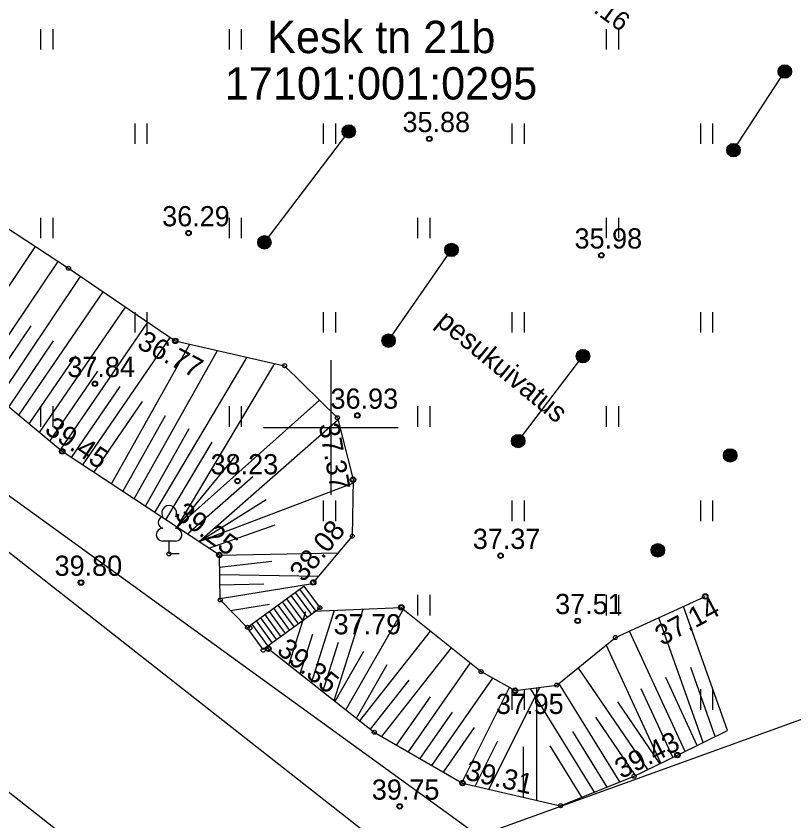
# Model space of a CAD drawing. Extents: x 641898 to 642452, y 6471715 to 6472255.
# Drawn here: x 642038.32 to 642067.2, y 6472085.4 to 6472115.26 of the extents above; entities that cross this region are included whole.
import ezdxf

# ---------------------------------------------------------------- set-up
doc = ezdxf.new("R2010")
doc.units = 0
for name, color, linetype in [('HALJASTUS', 7, 'Continuous'), ('HOONE', 7, 'Continuous'), ('KORGUS-EH2000', 7, 'Continuous'), ('MOOTMPUNKT', 7, 'Continuous'), ('MOOTPIIR', 7, 'Continuous'), ('PIIR', 7, 'Continuous'), ('PUU', 7, 'Continuous'), ('RAJATIS', 7, 'Continuous'), ('RELJEEF', 7, 'Continuous'), ('TEE', 7, 'Continuous'), ('VORK', 7, 'Continuous')]:
    doc.layers.add(name, color=color, linetype=linetype)

msp = doc.modelspace()

# ---------------------------------------------------------------- linework, layer by layer
at = {"layer": 'HALJASTUS'}
for p, q in [((642039.225, 6472114.782), (642039.225, 6472114.021)), ((642039.68, 6472114.782), (642039.68, 6472114.021)), ((642046.225, 6472114.782), (642046.225, 6472114.021)), ((642046.68, 6472114.782), (642046.68, 6472114.021)), ((642060.225, 6472114.782), (642060.225, 6472114.021)), ((642060.68, 6472114.782), (642060.68, 6472114.021)), ((642042.725, 6472111.282), (642042.725, 6472110.521)), ((642043.18, 6472111.282), (642043.18, 6472110.521)), ((642049.725, 6472111.282), (642049.725, 6472110.521)), ((642050.18, 6472111.282), (642050.18, 6472110.521)), ((642056.725, 6472111.282), (642056.725, 6472110.521)), ((642057.18, 6472111.282), (642057.18, 6472110.521)), ((642063.725, 6472111.282), (642063.725, 6472110.521)), ((642064.18, 6472111.282), (642064.18, 6472110.521)), ((642039.225, 6472107.782), (642039.225, 6472107.021)), ((642039.68, 6472107.782), (642039.68, 6472107.021)), ((642046.225, 6472107.782), (642046.225, 6472107.021)), ((642046.68, 6472107.782), (642046.68, 6472107.021)), ((642053.225, 6472107.782), (642053.225, 6472107.021)), ((642053.68, 6472107.782), (642053.68, 6472107.021)), ((642060.225, 6472107.782), (642060.225, 6472107.021)), ((642060.68, 6472107.782), (642060.68, 6472107.021)), ((642042.725, 6472104.282), (642042.725, 6472103.521)), ((642043.18, 6472104.282), (642043.18, 6472103.521)), ((642049.725, 6472104.282), (642049.725, 6472103.521)), ((642050.18, 6472104.282), (642050.18, 6472103.521)), ((642056.725, 6472104.282), (642056.725, 6472103.521)), ((642057.18, 6472104.282), (642057.18, 6472103.521)), ((642063.725, 6472104.282), (642063.725, 6472103.521)), ((642064.18, 6472104.282), (642064.18, 6472103.521)), ((642039.225, 6472100.782), (642039.225, 6472100.021)), ((642039.68, 6472100.782), (642039.68, 6472100.021)), ((642046.225, 6472100.782), (642046.225, 6472100.021)), ((642046.68, 6472100.782), (642046.68, 6472100.021)), ((642053.225, 6472100.782), (642053.225, 6472100.021)), ((642053.68, 6472100.782), (642053.68, 6472100.021)), ((642060.225, 6472100.782), (642060.225, 6472100.021)), ((642060.68, 6472100.782), (642060.68, 6472100.021)), ((642049.725, 6472097.282), (642049.725, 6472096.521)), ((642050.18, 6472097.282), (642050.18, 6472096.521)), ((642056.725, 6472097.282), (642056.725, 6472096.521)), ((642057.18, 6472097.282), (642057.18, 6472096.521)), ((642063.725, 6472097.282), (642063.725, 6472096.521)), ((642064.18, 6472097.282), (642064.18, 6472096.521)), ((642053.225, 6472093.782), (642053.225, 6472093.021)), ((642053.68, 6472093.782), (642053.68, 6472093.021)), ((642060.225, 6472093.782), (642060.225, 6472093.021)), ((642060.68, 6472093.782), (642060.68, 6472093.021)), ((642056.725, 6472090.282), (642056.725, 6472089.521)), ((642057.18, 6472090.282), (642057.18, 6472089.521)), ((642063.725, 6472090.282), (642063.725, 6472089.521)), ((642064.18, 6472090.282), (642064.18, 6472089.521))]:
    msp.add_line(p, q, dxfattribs=at)
at = {"layer": 'HOONE'}
msp.add_lwpolyline([(642065.653, 6472064.719), (642027.624, 6472094.67), (642021.622, 6472087.119), (642059.651, 6472057.168), (642065.653, 6472064.719)], dxfattribs=at)
at = {"layer": 'KORGUS-EH2000'}
for centre in [(642053.663, 6472110.708), (642044.723, 6472107.212), (642060.051, 6472106.387), (642044.229, 6472103.211), (642041.245, 6472101.619), (642050.992, 6472100.443), (642040.033, 6472099.108), (642046.54, 6472098.009), (642050.829, 6472098.064), (642045.866, 6472095.265), (642056.308, 6472095.24), (642040.73, 6472094.242), (642049.352, 6472094.247), (642063.908, 6472093.726), (642052.622, 6472093.318), (642059.17, 6472092.822), (642047.685, 6472091.788), (642056.844, 6472090.234), (642062.871, 6472087.84), (642054.894, 6472086.799), (642052.56, 6472085.936)]:
    msp.add_circle(centre, 0.1, dxfattribs=at)
at = {"layer": 'MOOTMPUNKT'}
for centre in [(642053.663, 6472110.708), (642044.723, 6472107.212), (642060.051, 6472106.387), (642040.265, 6472105.906), (642044.229, 6472103.211), (642048.288, 6472102.29), (642041.245, 6472101.619), (642050.25, 6472100.358), (642050.992, 6472100.443), (642040.033, 6472099.108), (642046.54, 6472098.009), (642050.829, 6472098.064), (642050.8, 6472095.965), (642044, 6472095.306), (642045.866, 6472095.265), (642056.308, 6472095.24), (642040.73, 6472094.242), (642049.352, 6472094.247), (642063.908, 6472093.726), (642045.899, 6472093.597), (642049.598, 6472093.306), (642052.622, 6472093.318), (642059.17, 6472092.822), (642046.91, 6472092.582), (642046.999, 6472092.554), (642060.571, 6472092.204), (642047.494, 6472091.733), (642047.685, 6472091.788), (642055.585, 6472090.939), (642058.392, 6472090.436), (642056.844, 6472090.234), (642051.619, 6472088.689), (642062.871, 6472087.84), (642054.894, 6472086.799), (642061.262, 6472087.055), (642052.56, 6472085.936), (642058.538, 6472085.962)]:
    msp.add_circle(centre, 0.075, dxfattribs=at)
at = {"layer": 'MOOTPIIR'}
msp.add_lwpolyline([(642014.306, 6472085.384), (642027.67, 6472104.979), (642055.501, 6472084.843), (642081.563, 6472094.262), (642123.938, 6472142.273), (642065.721, 6472244.475), (642008.922, 6472196.948), (642003.347, 6472200.453), (641979.65, 6472162.756), (641979.65, 6472162.756), (641986.045, 6472158.736), (642004.269, 6472142.365), (641987.048, 6472123.488), (641970.482, 6472097.889), (641986.758, 6472084.396)], close=True, dxfattribs=at)
at = {"layer": 'PIIR'}
msp.add_line((642016.19, 6472112.51), (642089.96, 6472054.66), dxfattribs=at)
at = {"layer": 'PUU'}
for p, q in [((642044.24, 6472095.781), (642043.76, 6472095.781)), ((642044, 6472095.306), (642044, 6472095.781)), ((642044.38, 6472095.306), (642044, 6472095.306))]:
    msp.add_line(p, q, dxfattribs=at)
for centre, radius, start, end in [((642044, 6472096.826), 0.277, 332.5799, 207.4201), ((642043.83, 6472096.479), 0.233, 109.0217, 253.1415), ((642044.17, 6472096.479), 0.233, 286.8508, 70.9859), ((642043.763, 6472096.018), 0.238, 90.0016, 269.3953), ((642044.237, 6472096.018), 0.238, 270.6047, 89.9984)]:
    msp.add_arc(centre, radius, start, end, dxfattribs=at)
at = {"layer": 'RAJATIS'}
for points in [[(642064.954, 6472110.286), (642066.862, 6472113.206)], [(642047.54, 6472106.867), (642050.672, 6472110.982)], [(642052.148, 6472103.221), (642054.486, 6472106.587)], [(642056.961, 6472099.492), (642059.366, 6472102.644)]]:
    msp.add_lwpolyline(points, dxfattribs=at)
for centre, radius in [((642066.862, 6472113.206), 0.25), ((642066.862, 6472113.206), 0.225), ((642066.862, 6472113.206), 0.2), ((642066.862, 6472113.206), 0.175), ((642066.862, 6472113.206), 0.15), ((642066.862, 6472113.206), 0.125), ((642066.862, 6472113.206), 0.1), ((642066.862, 6472113.206), 0.075), ((642066.862, 6472113.206), 0.05), ((642066.862, 6472113.206), 0.025), ((642050.672, 6472110.982), 0.25), ((642050.672, 6472110.982), 0.225), ((642050.672, 6472110.982), 0.2), ((642050.672, 6472110.982), 0.175), ((642050.672, 6472110.982), 0.15), ((642050.672, 6472110.982), 0.125), ((642050.672, 6472110.982), 0.1), ((642050.672, 6472110.982), 0.075), ((642050.672, 6472110.982), 0.05), ((642050.672, 6472110.982), 0.025), ((642064.954, 6472110.286), 0.25), ((642064.954, 6472110.286), 0.225), ((642064.954, 6472110.286), 0.2), ((642064.954, 6472110.286), 0.175), ((642064.954, 6472110.286), 0.15), ((642064.954, 6472110.286), 0.125), ((642064.954, 6472110.286), 0.1), ((642064.954, 6472110.286), 0.075), ((642064.954, 6472110.286), 0.05), ((642064.954, 6472110.286), 0.025), ((642047.54, 6472106.867), 0.25), ((642047.54, 6472106.867), 0.225), ((642047.54, 6472106.867), 0.2), ((642047.54, 6472106.867), 0.175), ((642047.54, 6472106.867), 0.15), ((642047.54, 6472106.867), 0.125), ((642047.54, 6472106.867), 0.1), ((642047.54, 6472106.867), 0.075), ((642047.54, 6472106.867), 0.05), ((642047.54, 6472106.867), 0.025), ((642054.486, 6472106.587), 0.25), ((642054.486, 6472106.587), 0.225), ((642054.486, 6472106.587), 0.2), ((642054.486, 6472106.587), 0.175), ((642054.486, 6472106.587), 0.15), ((642054.486, 6472106.587), 0.125), ((642054.486, 6472106.587), 0.1), ((642054.486, 6472106.587), 0.075), ((642054.486, 6472106.587), 0.05), ((642054.486, 6472106.587), 0.025), ((642052.148, 6472103.221), 0.25), ((642052.148, 6472103.221), 0.225), ((642052.148, 6472103.221), 0.2), ((642052.148, 6472103.221), 0.175), ((642052.148, 6472103.221), 0.15), ((642052.148, 6472103.221), 0.125), ((642052.148, 6472103.221), 0.1), ((642052.148, 6472103.221), 0.075), ((642052.148, 6472103.221), 0.05), ((642052.148, 6472103.221), 0.025), ((642059.366, 6472102.644), 0.25), ((642059.366, 6472102.644), 0.225), ((642059.366, 6472102.644), 0.2), ((642059.366, 6472102.644), 0.175), ((642059.366, 6472102.644), 0.15), ((642059.366, 6472102.644), 0.125), ((642059.366, 6472102.644), 0.1), ((642059.366, 6472102.644), 0.075), ((642059.366, 6472102.644), 0.05), ((642059.366, 6472102.644), 0.025), ((642056.961, 6472099.492), 0.25), ((642056.961, 6472099.492), 0.225), ((642056.961, 6472099.492), 0.2), ((642056.961, 6472099.492), 0.175), ((642056.961, 6472099.492), 0.15), ((642056.961, 6472099.492), 0.125), ((642056.961, 6472099.492), 0.1), ((642056.961, 6472099.492), 0.075), ((642056.961, 6472099.492), 0.05), ((642056.961, 6472099.492), 0.025), ((642064.83, 6472098.96), 0.25), ((642064.83, 6472098.96), 0.225), ((642064.83, 6472098.96), 0.2), ((642064.83, 6472098.96), 0.175), ((642064.83, 6472098.96), 0.15), ((642064.83, 6472098.96), 0.125), ((642064.83, 6472098.96), 0.1), ((642064.83, 6472098.96), 0.075), ((642064.83, 6472098.96), 0.05), ((642064.83, 6472098.96), 0.025), ((642062.145, 6472095.439), 0.25), ((642062.145, 6472095.439), 0.225), ((642062.145, 6472095.439), 0.2), ((642062.145, 6472095.439), 0.175), ((642062.145, 6472095.439), 0.15), ((642062.145, 6472095.439), 0.125), ((642062.145, 6472095.439), 0.1), ((642062.145, 6472095.439), 0.075), ((642062.145, 6472095.439), 0.05), ((642062.145, 6472095.439), 0.025)]:
    msp.add_circle(centre, radius, dxfattribs=at)
at = {"layer": 'RELJEEF'}
for p, q in [((642036.119, 6472102.358), (642039.042, 6472106.707)), ((642036.893, 6472101.716), (642039.879, 6472106.159)), ((642037.666, 6472101.073), (642040.71, 6472105.603)), ((642038.418, 6472100.449), (642041.556, 6472105.028)), ((642039.191, 6472099.808), (642042.383, 6472104.466)), ((642039.963, 6472099.166), (642043.21, 6472103.904)), ((642037.279, 6472101.395), (642038.878, 6472103.773)), ((642040.793, 6472098.607), (642044.037, 6472103.341)), ((642038.053, 6472100.752), (642039.708, 6472103.216)), ((642041.866, 6472097.9), (642044.776, 6472103.087)), ((642042.703, 6472097.349), (642045.793, 6472102.856)), ((642038.804, 6472100.128), (642040.535, 6472102.653)), ((642043.465, 6472096.847), (642046.904, 6472102.604)), ((642039.577, 6472099.487), (642041.36, 6472102.088)), ((642044.301, 6472096.296), (642047.929, 6472102.371)), ((642040.375, 6472098.883), (642042.184, 6472101.523)), ((642041.21, 6472098.332), (642043.009, 6472100.957)), ((642044.301, 6472096.296), (642049.59, 6472101.008)), ((642042.285, 6472097.625), (642043.868, 6472100.446)), ((642045.113, 6472095.761), (642050.271, 6472100.275)), ((642043.122, 6472097.073), (642044.74, 6472099.957)), ((642043.883, 6472096.572), (642045.6, 6472099.447)), ((642044.301, 6472096.296), (642046.452, 6472098.926)), ((642044.68, 6472096.046), (642047.111, 6472098.174)), ((642045.113, 6472095.761), (642050.827, 6472097.926)), ((642045.113, 6472095.761), (642047.608, 6472097.327)), ((642045.478, 6472095.521), (642047.939, 6472096.384)), ((642045.866, 6472095.265), (642050.278, 6472095.346)), ((642045.875, 6472094.817), (642047.816, 6472095.037)), ((642045.88, 6472094.545), (642049.552, 6472094.484)), ((642045.888, 6472094.156), (642047.513, 6472094.191)), ((642045.898, 6472093.651), (642049.323, 6472094.213)), ((642046.28, 6472093.207), (642047.726, 6472093.444)), ((642048.449, 6472091.186), (642049.083, 6472093.17)), ((642049.288, 6472090.525), (642050.146, 6472093.215)), ((642050.127, 6472089.864), (642051.21, 6472093.259)), ((642050.562, 6472089.522), (642052.702, 6472093.254)), ((642064.732, 6472088.748), (642063.094, 6472093.355)), ((642063.828, 6472088.307), (642062.18, 6472092.938)), ((642048.869, 6472090.855), (642049.342, 6472092.339)), ((642051.088, 6472089.107), (642053.711, 6472092.444)), ((642063.156, 6472087.979), (642061.094, 6472092.443)), ((642049.708, 6472090.195), (642050.295, 6472092.035)), ((642062.257, 6472087.54), (642060.231, 6472091.928)), ((642050.164, 6472089.835), (642051.232, 6472091.696)), ((642051.903, 6472088.525), (642054.491, 6472091.818)), ((642050.959, 6472089.209), (642052.099, 6472091.198)), ((642052.884, 6472087.959), (642055.186, 6472091.259)), ((642061.769, 6472087.302), (642059.192, 6472091.085)), ((642064.28, 6472088.527), (642063.37, 6472091.085)), ((642051.481, 6472088.798), (642052.909, 6472090.615)), ((642053.754, 6472087.457), (642056.014, 6472090.699)), ((642060.736, 6472086.844), (642058.476, 6472090.504)), ((642063.605, 6472088.198), (642062.439, 6472090.723)), ((642054.872, 6472086.812), (642056.641, 6472090.348)), ((642055.871, 6472086.575), (642057.762, 6472090.354)), ((642059.794, 6472086.466), (642057.421, 6472090.309)), ((642057.656, 6472086.165), (642057.656, 6472090.34)), ((642062.706, 6472087.76), (642061.531, 6472090.303)), ((642052.449, 6472088.21), (642053.702, 6472090.006)), ((642062.223, 6472087.524), (642060.664, 6472089.813)), ((642053.318, 6472087.708), (642054.522, 6472089.434)), ((642061.315, 6472087.081), (642059.838, 6472089.25)), ((642054.188, 6472087.206), (642055.343, 6472088.862)), ((642060.265, 6472086.655), (642058.994, 6472088.712)), ((642055.37, 6472086.69), (642056.21, 6472088.369)), ((642057.156, 6472086.279), (642057.156, 6472088.142)), ((642059.323, 6472086.277), (642058.144, 6472088.187))]:
    msp.add_line(p, q, dxfattribs=at)
for points in [[(642024.308, 6472114.721), (642030.362, 6472113.989), (642036.333, 6472108.482), (642040.265, 6472105.906), (642044.229, 6472103.211), (642048.288, 6472102.29), (642050.25, 6472100.358), (642050.829, 6472098.064), (642050.8, 6472095.965), (642049.352, 6472094.247)], [(642046.898, 6472092.573), (642045.899, 6472093.597), (642045.866, 6472095.265), (642040.033, 6472099.108), (642035.046, 6472103.249), (642029.201, 6472104.902), (642019.993, 6472109.094), (642016.735, 6472110.959)], [(642049.365, 6472093.182), (642052.622, 6472093.318), (642055.585, 6472090.939), (642056.844, 6472090.234), (642058.392, 6472090.436), (642060.571, 6472092.204), (642063.908, 6472093.726)], [(642047.617, 6472091.841), (642051.619, 6472088.689), (642054.894, 6472086.799), (642058.538, 6472085.962), (642061.262, 6472087.055), (642062.871, 6472087.84), (642064.732, 6472088.748)]]:
    msp.add_lwpolyline(points, dxfattribs=at)
at = {"layer": 'TEE'}
for p, q in [((642048.523, 6472093.76), (642049.122, 6472092.94)), ((642048.685, 6472093.878), (642049.284, 6472093.058)), ((642048.846, 6472093.996), (642049.445, 6472093.176)), ((642048.2, 6472093.524), (642048.799, 6472092.704)), ((642048.362, 6472093.642), (642048.961, 6472092.822)), ((642047.716, 6472093.17), (642048.315, 6472092.35)), ((642047.877, 6472093.288), (642048.476, 6472092.468)), ((642048.039, 6472093.406), (642048.638, 6472092.586)), ((642047.393, 6472092.935), (642047.992, 6472092.115)), ((642047.554, 6472093.052), (642048.153, 6472092.232)), ((642047.07, 6472092.699), (642047.669, 6472091.879)), ((642047.231, 6472092.817), (642047.83, 6472091.997))]:
    msp.add_line(p, q, dxfattribs=at)
msp.add_lwpolyline([(642049.607, 6472093.294), (642047.497, 6472091.753), (642046.898, 6472092.573), (642049.008, 6472094.114), (642049.607, 6472093.294)], dxfattribs=at)
at = {"layer": 'VORK'}
for p, q in [((642050, 6472102.5), (642050, 6472097.5)), ((642047.5, 6472100), (642052.5, 6472100))]:
    msp.add_line(p, q, dxfattribs=at)

# ---------------------------------------------------------------- texts
at = {"layer": 'KORGUS-EH2000'}
for s, height, rotation, p in [('35.16', 0.7, 323.9474, (642058.882, 6472116.04)), ('36.77', 0.75, 332.1394, (642042.77, 6472102.969)), ('39.45', 0.75, 326.064, (642039.336, 6472099.824)), ('37.37', 0.75, 280.1832, (642049.556, 6472100.095)), ('39.25', 0.75, 324.1741, (642044.164, 6472096.673)), ('38.08', 0.75, 50.668, (642048.99, 6472094.222)), ('37.14', 0.75, 28.2577, (642062.3, 6472091.881)), ('39.35', 0.75, 321.1626, (642047.957, 6472091.655)), ('39.43', 0.75, 27.0535, (642060.795, 6472086.943)), ('39.31', 0.75, 347.0997, (642054.955, 6472086.942))]:
    msp.add_text(s, height=height, rotation=rotation, dxfattribs=at).set_placement(p)
for s, p in [('35.88', (642052.665, 6472110.958)), ('36.29', (642043.743, 6472107.462)), ('35.98', (642059.053, 6472106.637)), ('37.84', (642040.224, 6472101.869)), ('36.93', (642049.994, 6472100.693)), ('38.23', (642045.542, 6472098.259)), ('37.37', (642055.275, 6472095.49)), ('39.80', (642039.748, 6472094.492)), ('37.51', (642058.333, 6472093.072)), ('37.79', (642050.108, 6472092.321)), ('37.95', (642056.138, 6472089.365)), ('39.75', (642051.527, 6472086.186))]:
    msp.add_text(s, height=0.75, dxfattribs=at).set_placement(p)
at = {"layer": 'PIIR'}
for s, p in [('Kesk tn 21b', (642047.64, 6472113.887)), ('17101:001:0295', (642046.069, 6472112.167))]:
    msp.add_text(s, height=1.2, dxfattribs=at).set_placement(p)
at = {"layer": 'RAJATIS'}
msp.add_text('pesukuivatus', height=0.75, rotation=320.6014, dxfattribs=at).set_placement((642053.876, 6472103.841))

doc.saveas('drawing.dxf')
